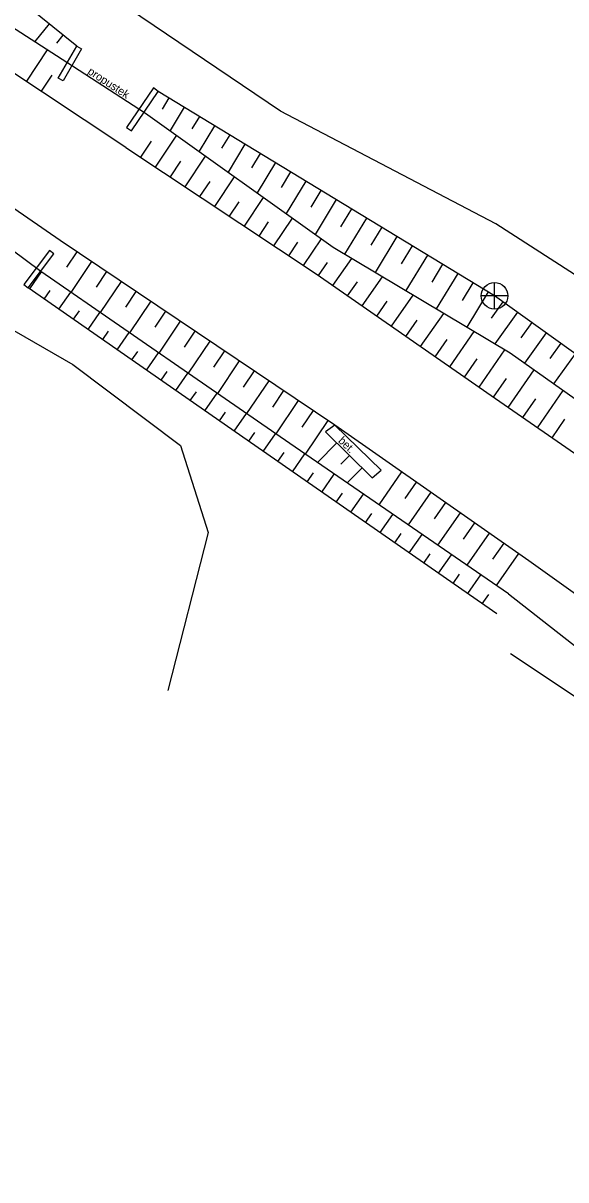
# Model space of a CAD drawing. Extents: x -747135 to -746147, y -1093269 to -1091735.
# Drawn here: x -746814 to -746783.5, y -1092415.2 to -1092350.2 of the extents above; entities that cross this region are included whole.
import ezdxf

# ---------------------------------------------------------------- set-up
doc = ezdxf.new("R2010")
doc.units = 0
for name, color, linetype in [('101', 7, 'Continuous'), ('1016', 7, 'Continuous'), ('105', 7, 'Continuous'), ('23700', 7, 'Continuous'), ('305', 7, 'Continuous'), ('316', 7, 'Continuous'), ('424', 7, 'Continuous')]:
    doc.layers.add(name, color=color, linetype=linetype)

msp = doc.modelspace()

# ---------------------------------------------------------------- linework, layer by layer
at = {"layer": '101'}
for points in [[(-746886.98, -1092300.01), (-746879.5, -1092306.35), (-746871.83, -1092312.38), (-746860.78, -1092320.38), (-746850.53, -1092327.24), (-746833.2, -1092338.57), (-746822.17, -1092345.53), (-746811.56, -1092352.38)], [(-746810.99, -1092351.49), (-746819.19, -1092344.86), (-746827.07, -1092338.73), (-746839.09, -1092330.7), (-746851.03, -1092322.46), (-746859.35, -1092317.66), (-746865.37, -1092313.34), (-746867.07, -1092310.73), (-746878.25, -1092302.71)], [(-746812.545, -1092350.233), (-746813.348, -1092351.226)], [(-746811.768, -1092350.861), (-746812.135, -1092351.316)], [(-746813.806, -1092353.457), (-746812.63, -1092351.689)], [(-746812.974, -1092354.011), (-746812.382, -1092353.121)], [(-746676.31, -1092494.93), (-746679.28, -1092488.1), (-746684.61, -1092481.19), (-746692.58, -1092466.75), (-746703.9, -1092446.01), (-746716.46, -1092426.76), (-746727.325, -1092413.107), (-746739.95, -1092401.9), (-746747.98, -1092394.64), (-746752.03, -1092391.71), (-746753.83, -1092389.76), (-746758.64, -1092386.23), (-746765.82, -1092381.07), (-746787.5, -1092365.52), (-746806.41, -1092354.03)], [(-746805.808, -1092354.396), (-746806.185, -1092355.017)], [(-746807.12, -1092355.24), (-746796.58, -1092362.79), (-746786.63, -1092368.73), (-746775.02, -1092376.93), (-746764.6, -1092384.11), (-746753.89, -1092392.74), (-746744.6, -1092400.27), (-746734.99, -1092408.91), (-746726.93, -1092417.05), (-746720.19, -1092425.45), (-746712.76, -1092435.88), (-746705, -1092448.32), (-746698.55, -1092460.04), (-746691.76, -1092472.37), (-746682.53, -1092488.74), (-746678.42, -1092495.91)], [(-746804.953, -1092354.915), (-746805.748, -1092356.223)], [(-746804.099, -1092355.434), (-746804.516, -1092356.121)], [(-746803.244, -1092355.954), (-746804.117, -1092357.391)], [(-746806.563, -1092358.278), (-746805.373, -1092356.491)], [(-746802.389, -1092356.473), (-746802.846, -1092357.224)], [(-746807.395, -1092357.724), (-746806.791, -1092356.816)], [(-746801.535, -1092356.992), (-746802.487, -1092358.559)], [(-746805.73, -1092358.832), (-746805.145, -1092357.953)], [(-746804.898, -1092359.386), (-746803.746, -1092357.657)], [(-746800.68, -1092357.512), (-746801.176, -1092358.327)], [(-746799.826, -1092358.031), (-746800.856, -1092359.727)], [(-746798.971, -1092358.55), (-746799.506, -1092359.431)], [(-746804.065, -1092359.94), (-746803.499, -1092359.09)], [(-746803.233, -1092360.494), (-746802.12, -1092358.822)], [(-746798.116, -1092359.069), (-746799.226, -1092360.895)], [(-746801.568, -1092361.602), (-746800.493, -1092359.987)], [(-746797.262, -1092359.589), (-746797.836, -1092360.534)], [(-746802.4, -1092361.048), (-746801.853, -1092360.226)], [(-746796.407, -1092360.108), (-746797.595, -1092362.063)], [(-746795.552, -1092360.627), (-746796.166, -1092361.637)], [(-746800.735, -1092362.156), (-746800.207, -1092361.363)], [(-746799.903, -1092362.711), (-746798.866, -1092361.153)], [(-746794.698, -1092361.146), (-746795.932, -1092363.177)], [(-746793.843, -1092361.666), (-746794.458, -1092362.678)], [(-746799.07, -1092363.265), (-746798.561, -1092362.5)], [(-746798.238, -1092363.819), (-746797.239, -1092362.318)], [(-746792.989, -1092362.185), (-746794.214, -1092364.202)], [(-746810.986, -1092363.038), (-746811.564, -1092363.897)], [(-746792.134, -1092362.704), (-746792.745, -1092363.71)], [(-746791.279, -1092363.224), (-746792.497, -1092365.227)], [(-746810.156, -1092363.596), (-746811.318, -1092365.325)], [(-746797.407, -1092364.375), (-746796.897, -1092363.641)], [(-746796.586, -1092364.946), (-746795.525, -1092363.42)], [(-746790.425, -1092363.743), (-746791.032, -1092364.741)], [(-746813.639, -1092365.126), (-746812.98, -1092364.178)], [(-746786.72, -1092382.28), (-746799.01, -1092373.82), (-746813.02, -1092364.15)], [(-746809.326, -1092364.153), (-746809.911, -1092365.023)], [(-746794.944, -1092366.088), (-746793.804, -1092364.447)], [(-746789.57, -1092364.262), (-746790.78, -1092366.253)], [(-746787.37, -1092383.4), (-746813.72, -1092365.07)], [(-746812.818, -1092365.697), (-746812.487, -1092365.222)], [(-746808.496, -1092364.711), (-746809.672, -1092366.461)], [(-746795.765, -1092365.517), (-746795.215, -1092364.725)], [(-746788.716, -1092364.781), (-746789.318, -1092365.773)], [(-746811.997, -1092366.268), (-746811.334, -1092365.314)], [(-746807.666, -1092365.269), (-746808.258, -1092366.149)], [(-746806.836, -1092365.827), (-746808.026, -1092367.597)], [(-746794.123, -1092366.658), (-746793.533, -1092365.81)], [(-746793.302, -1092367.229), (-746792.082, -1092365.475)], [(-746787.861, -1092365.301), (-746789.062, -1092367.278)], [(-746787.031, -1092365.857), (-746787.692, -1092366.779)], [(-746811.176, -1092366.839), (-746810.843, -1092366.361)], [(-746810.356, -1092367.41), (-746809.688, -1092366.45)], [(-746806.006, -1092366.385), (-746806.604, -1092367.275)], [(-746791.659, -1092368.371), (-746790.361, -1092366.503)], [(-746786.218, -1092366.439), (-746787.492, -1092368.215)], [(-746805.176, -1092366.942), (-746806.38, -1092368.733)], [(-746792.481, -1092367.8), (-746791.851, -1092366.894)], [(-746785.405, -1092367.022), (-746786.018, -1092367.876)], [(-746809.535, -1092367.982), (-746809.2, -1092367.5)], [(-746808.714, -1092368.553), (-746808.042, -1092367.586)], [(-746804.346, -1092367.5), (-746804.951, -1092368.401)], [(-746790.017, -1092369.512), (-746788.64, -1092367.53)], [(-746784.593, -1092367.605), (-746785.813, -1092369.307)], [(-746803.516, -1092368.058), (-746804.734, -1092369.869)], [(-746790.838, -1092368.941), (-746790.169, -1092367.979)], [(-746783.78, -1092368.188), (-746784.388, -1092369.036)], [(-746807.893, -1092369.124), (-746807.556, -1092368.639)], [(-746807.072, -1092369.695), (-746806.396, -1092368.722)], [(-746802.686, -1092368.616), (-746803.298, -1092369.527)], [(-746789.196, -1092370.083), (-746788.488, -1092369.064)], [(-746788.375, -1092370.654), (-746786.918, -1092368.558)], [(-746782.968, -1092368.771), (-746784.18, -1092370.461)], [(-746806.251, -1092370.266), (-746805.912, -1092369.778)], [(-746801.856, -1092369.174), (-746803.088, -1092371.006)], [(-746801.026, -1092369.731), (-746801.645, -1092370.653)], [(-746786.731, -1092371.793), (-746785.276, -1092369.687)], [(-746805.43, -1092370.837), (-746804.75, -1092369.858)], [(-746800.196, -1092370.289), (-746801.441, -1092372.142)], [(-746787.554, -1092371.224), (-746786.823, -1092370.167)], [(-746804.609, -1092371.408), (-746804.268, -1092370.917)], [(-746803.788, -1092371.979), (-746803.104, -1092370.995)], [(-746799.366, -1092370.847), (-746799.992, -1092371.778)], [(-746785.086, -1092372.93), (-746783.642, -1092370.84)], [(-746798.536, -1092371.405), (-746799.795, -1092373.278)], [(-746785.908, -1092372.361), (-746785.184, -1092371.312)], [(-746802.967, -1092372.55), (-746802.624, -1092372.056)], [(-746802.146, -1092373.121), (-746801.458, -1092372.131)], [(-746797.706, -1092371.963), (-746798.339, -1092372.904)], [(-746796.876, -1092372.52), (-746798.148, -1092374.413)], [(-746784.263, -1092373.498), (-746783.544, -1092372.458)], [(-746801.325, -1092373.692), (-746800.98, -1092373.195)], [(-746800.505, -1092374.263), (-746799.812, -1092373.267)], [(-746799.684, -1092374.834), (-746799.336, -1092374.334)], [(-746796.377, -1092373.786), (-746797.463, -1092374.885)], [(-746798.863, -1092375.405), (-746798.165, -1092374.402)], [(-746795.666, -1092374.489), (-746796.146, -1092374.975)], [(-746798.042, -1092375.976), (-746797.691, -1092375.473)], [(-746797.221, -1092376.547), (-746796.517, -1092375.536)], [(-746794.954, -1092375.192), (-746795.79, -1092376.037)], [(-746792.726, -1092375.421), (-746794.01, -1092377.262)], [(-746791.905, -1092375.993), (-746792.546, -1092376.911)], [(-746796.4, -1092377.118), (-746796.047, -1092376.611)], [(-746795.579, -1092377.689), (-746794.87, -1092376.67)], [(-746791.085, -1092376.564), (-746792.362, -1092378.396)], [(-746790.265, -1092377.136), (-746790.902, -1092378.05)], [(-746794.758, -1092378.261), (-746794.402, -1092377.749)], [(-746793.937, -1092378.832), (-746793.222, -1092377.804)], [(-746789.444, -1092377.708), (-746790.715, -1092379.53)], [(-746793.116, -1092379.403), (-746792.758, -1092378.887)], [(-746788.624, -1092378.28), (-746789.258, -1092379.189)], [(-746787.804, -1092378.852), (-746789.067, -1092380.664)], [(-746792.295, -1092379.974), (-746791.575, -1092378.938)], [(-746786.984, -1092379.424), (-746787.614, -1092380.328)], [(-746791.475, -1092380.545), (-746791.113, -1092380.025)], [(-746790.654, -1092381.116), (-746789.928, -1092380.072)], [(-746786.163, -1092379.996), (-746787.42, -1092381.798)], [(-746789.833, -1092381.687), (-746789.468, -1092381.163)], [(-746789.012, -1092382.258), (-746788.28, -1092381.206)], [(-746788.191, -1092382.829), (-746787.824, -1092382.301)]]:
    msp.add_lwpolyline(points, dxfattribs=at)
at = {"layer": '1016'}
for points in [[(-746887.66, -1092302.09), (-746880.53, -1092307.62), (-746872.41, -1092313.76), (-746861.83, -1092321.34), (-746850.87, -1092329.15), (-746834.21, -1092340.08), (-746822.74, -1092347.51), (-746812.918, -1092354.047)], [(-746812.04, -1092353.28), (-746810.99, -1092351.49), (-746810.73, -1092351.64), (-746811.762, -1092353.434), (-746812.04, -1092353.28)], [(-746812.916, -1092354.049), (-746808.229, -1092357.169)], [(-746807.92, -1092356.25), (-746806.41, -1092354.03), (-746806.67, -1092353.83), (-746808.188, -1092356.058), (-746807.92, -1092356.25)], [(-746808.227, -1092357.17), (-746797.53, -1092364.29), (-746787.69, -1092371.13), (-746776.62, -1092378.78), (-746765.54, -1092386.79), (-746755.3, -1092394.62), (-746745.57, -1092402.66), (-746737.91, -1092409.79), (-746728.85, -1092419.26), (-746722.7, -1092426.86), (-746714.67, -1092437.95), (-746707.62, -1092449.35), (-746700.44, -1092461.3), (-746693.84, -1092472.82), (-746684.01, -1092490.2), (-746680.08, -1092497.02)], [(-746774.902, -1092388.005), (-746776.84, -1092386.65), (-746785.57, -1092380.41), (-746796.49, -1092372.78), (-746811.92, -1092362.41), (-746816.377, -1092359.347)], [(-746813.72, -1092365.07), (-746812.29, -1092363.15), (-746812.53, -1092362.97), (-746813.962, -1092364.883), (-746813.72, -1092365.07)], [(-746796.49, -1092372.78), (-746797.01, -1092373.16), (-746794.39, -1092375.75), (-746793.87, -1092375.31), (-746796.49, -1092372.78)]]:
    msp.add_lwpolyline(points, dxfattribs=at)
at = {"layer": '23700'}
for points in [[(-746811.56, -1092352.38), (-746807.12, -1092355.24)], [(-746813.02, -1092364.15), (-746817.21, -1092361.03)], [(-746786.72, -1092382.28), (-746776.53, -1092390.25)]]:
    msp.add_lwpolyline(points, dxfattribs=at)
at = {"layer": '305'}
msp.add_lwpolyline([(-746786.6, -1092385.62), (-746781.22, -1092389.21)], dxfattribs=at)
at = {"layer": '316'}
for p, q in [((-746787.501, -1092366.268), (-746787.5, -1092364.773)), ((-746786.748, -1092365.526), (-746788.248, -1092365.521))]:
    msp.add_line(p, q, dxfattribs=at)
msp.add_circle((-746787.5, -1092365.52), 0.75, dxfattribs=at)
at = {"layer": '424'}
for points in [[(-746938.71, -1092286.05), (-746933.44, -1092286.22), (-746925.65, -1092289.67), (-746915.11, -1092297.76), (-746902.08, -1092308.43), (-746888.12, -1092318.25), (-746871.41, -1092330.26), (-746860.11, -1092339.08), (-746848.88, -1092347.29), (-746835.4, -1092355.44), (-746822.64, -1092362.8), (-746811.22, -1092369.37), (-746805.16, -1092373.94), (-746803.6, -1092378.83), (-746805.87, -1092387.71)], [(-746666.48, -1092509.53), (-746671.18, -1092501.38), (-746679.28, -1092488.1), (-746683.01, -1092480.66), (-746691.02, -1092465.89), (-746695.91, -1092457.38), (-746697.67, -1092451.5), (-746700.29, -1092444.13), (-746704.56, -1092439.88), (-746720.11, -1092421.5), (-746727.2, -1092412.89), (-746738.25, -1092401.15), (-746749.37, -1092389.72), (-746764.79, -1092376.86), (-746776.64, -1092368.43), (-746787.43, -1092361.47), (-746799.53, -1092355.13), (-746817.34, -1092343.1), (-746824.75, -1092337.86), (-746838.2, -1092329.38), (-746851.64, -1092319.28), (-746869.05, -1092306.53), (-746874.05, -1092300.95)]]:
    msp.add_lwpolyline(points, dxfattribs=at)

# ---------------------------------------------------------------- texts
at = {"layer": '105'}
for s, rotation, p in [('propustek', 326.82208, (-746810.422, -1092353.005)), ('bet.', 315.83832, (-746796.325, -1092373.704))]:
    msp.add_text(s, height=0.45, rotation=rotation, dxfattribs=at).set_placement(p)

doc.saveas('drawing.dxf')
